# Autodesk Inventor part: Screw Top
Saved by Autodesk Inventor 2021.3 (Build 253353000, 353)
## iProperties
Created: 2022-08
Part Number: Screw Top
Material: Generic
Document SubType Name: Modeling
Designer: Administrator
Density: 1 g/cm^3
Appearance: Default
Title: Screw Top
Author: Administrator
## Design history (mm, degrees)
feature "Screw Top"
body "Solid1"
